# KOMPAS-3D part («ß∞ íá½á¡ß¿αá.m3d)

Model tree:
1. Эскиз:2
2. Операция выдавливания:2
     Расстояние 1 = 19
3. Эскиз:3
4. Операция выдавливания:3
     Расстояние 1 = 3.8
5. Эскиз:4
6. Операция выдавливания:4
     Расстояние 1 = 4.4
7. Условное изображение резьбы:1
     Длина резьбы = 19; Шаг резьбы = 1.5; Номинальный диаметр резьбы = 4
8. Условное изображение резьбы:2
     Длина резьбы = 4.4; Шаг резьбы = 1.5; Номинальный диаметр резьбы = 4
9. Скругление:1
     Радиус = 0.1
